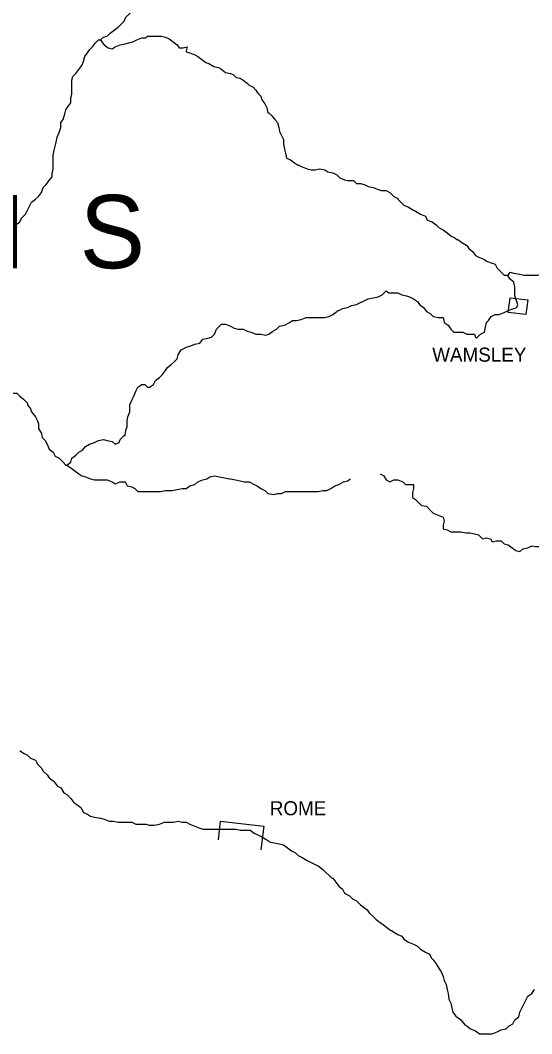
# Model space of a CAD drawing. Extents: x 0 to 40.2, y 0 to 22.
# Drawn here: x 4.348 to 5.056, y 15.833 to 17.238 of the extents above; entities that cross this region are included whole.
import ezdxf

# ---------------------------------------------------------------- set-up
doc = ezdxf.new("R2010")
doc.units = 0
doc.layers.add('Default', color=7, linetype='Continuous')
doc.layers.add('TR_Turning_Path1', color=7, linetype='Continuous')

msp = doc.modelspace()

# ---------------------------------------------------------------- linework, layer by layer
at = {"layer": 'Default'}
for points in [[(4.4914, 17.2361), (4.4941, 17.2416), (4.4996, 17.247), (4.5023, 17.2511), (4.5064, 17.2566), (4.5105, 17.262), (4.5146, 17.2675), (4.5187, 17.2716), (4.5214, 17.2784), (4.5268, 17.2825), (4.5296, 17.2879), (4.5337, 17.2934), (4.5364, 17.2975), (4.5418, 17.3043), (4.5432, 17.3084), (4.5459, 17.3139), (4.5487, 17.3179), (4.5487, 17.3193)], [(4.4587, 17.2102), (4.4628, 17.2143), (4.4682, 17.2157), (4.4723, 17.2198), (4.4778, 17.2239), (4.4832, 17.228), (4.4859, 17.2307), (4.4914, 17.2361), (4.4914, 17.2361)], [(4.3919, 17.0248), (4.3932, 17.0316), (4.3932, 17.0371), (4.3932, 17.0439), (4.3932, 17.0507), (4.3946, 17.0575), (4.396, 17.063), (4.3973, 17.0684), (4.3987, 17.0753), (4.4014, 17.0821), (4.4041, 17.0889), (4.4041, 17.0957), (4.4069, 17.0998), (4.4096, 17.108), (4.411, 17.1134), (4.4137, 17.1175), (4.4178, 17.123), (4.4178, 17.1298), (4.4191, 17.1352), (4.4191, 17.1421), (4.4191, 17.1489), (4.4191, 17.1543), (4.4205, 17.1598), (4.4246, 17.1639), (4.4287, 17.1693), (4.4328, 17.1748), (4.4355, 17.1802), (4.4369, 17.1871), (4.4409, 17.1925), (4.4437, 17.1966), (4.4478, 17.2007), (4.4519, 17.2061), (4.4559, 17.2102), (4.4559, 17.2102), (4.4587, 17.2102)], [(4.4587, 17.2102), (4.4614, 17.2061), (4.4641, 17.2034)], [(4.4641, 17.2034), (4.4696, 17.1993), (4.475, 17.198), (4.4791, 17.2007), (4.4859, 17.2034), (4.4928, 17.2048), (4.4982, 17.2061), (4.5037, 17.2075), (4.5091, 17.2102), (4.5159, 17.213), (4.5214, 17.213), (4.5241, 17.2157), (4.5309, 17.2157), (4.5364, 17.2157), (4.5432, 17.2157), (4.5487, 17.2143), (4.5541, 17.2116), (4.5596, 17.2075), (4.565, 17.2034), (4.5677, 17.1993), (4.5732, 17.1993), (4.5787, 17.2007), (4.5773, 17.1952), (4.5773, 17.1939)], [(4.5773, 17.1939), (4.5827, 17.1925), (4.5896, 17.1898), (4.5937, 17.1871), (4.5991, 17.183), (4.6046, 17.1789), (4.6086, 17.1775), (4.6155, 17.1734), (4.6223, 17.1721), (4.625, 17.1707), (4.6318, 17.1652), (4.6386, 17.1639), (4.6427, 17.1625), (4.6468, 17.1584), (4.6523, 17.1571), (4.6564, 17.1543), (4.6618, 17.1502), (4.6645, 17.1475), (4.67, 17.1448), (4.6741, 17.1407), (4.6768, 17.1366), (4.6809, 17.1325), (4.6823, 17.1271), (4.6864, 17.1216), (4.6891, 17.1162), (4.6905, 17.1093), (4.6918, 17.1093)], [(4.6918, 17.1093), (4.6959, 17.1052), (4.7, 17.0998), (4.7041, 17.0957), (4.7055, 17.0889), (4.7068, 17.0834), (4.7095, 17.078), (4.7123, 17.0725), (4.7123, 17.0657), (4.7136, 17.0589), (4.715, 17.0534), (4.7164, 17.0466), (4.7218, 17.0439), (4.7273, 17.0398), (4.7314, 17.0371), (4.7314, 17.0371), (4.7327, 17.0371)], [(4.7327, 17.0371), (4.7382, 17.0344), (4.745, 17.0316), (4.7504, 17.0303), (4.7559, 17.0303), (4.7627, 17.0316), (4.7695, 17.0303), (4.7736, 17.0275), (4.7804, 17.0262), (4.7859, 17.0234), (4.79, 17.0194), (4.7968, 17.0166), (4.8009, 17.0153), (4.8091, 17.0153), (4.8132, 17.0112), (4.8186, 17.0112), (4.8241, 17.0098), (4.8295, 17.0071), (4.8363, 17.0057), (4.8432, 17.003), (4.8472, 17.0016), (4.8541, 17.0016), (4.8595, 16.9989), (4.865, 16.9934), (4.8704, 16.9907), (4.8704, 16.9894)], [(4.3114, 16.9444), (4.3182, 16.9485), (4.3223, 16.9498), (4.3305, 16.9498), (4.336, 16.9498), (4.3414, 16.9539), (4.3469, 16.958), (4.3496, 16.9635), (4.3551, 16.9689), (4.3578, 16.9744), (4.3605, 16.9798), (4.3632, 16.9853), (4.3687, 16.9894), (4.3728, 16.9934), (4.3769, 16.9989), (4.3796, 17.0057), (4.3837, 17.0098), (4.3878, 17.0153), (4.3919, 17.0207), (4.3919, 17.0248)], [(4.8704, 16.9894), (4.8745, 16.9853), (4.8786, 16.9812), (4.8854, 16.9785), (4.8922, 16.9744), (4.895, 16.973), (4.9018, 16.9689), (4.9086, 16.9662), (4.9113, 16.9607), (4.9181, 16.958), (4.9236, 16.9539), (4.9277, 16.9498), (4.9331, 16.9471), (4.9386, 16.943), (4.944, 16.9389), (4.9495, 16.9362), (4.9522, 16.9335), (4.9536, 16.9335)], [(4.9536, 16.9335), (4.959, 16.9294), (4.9659, 16.9253), (4.9686, 16.9212), (4.974, 16.9171), (4.9781, 16.9116), (4.9836, 16.9089), (4.9904, 16.9062), (4.9931, 16.9035), (5.0013, 16.9007), (5.0054, 16.8994), (5.0081, 16.8939), (5.0136, 16.8885), (5.0177, 16.8844), (5.0231, 16.8844)], [(4.9795, 16.7971), (4.985, 16.8026), (4.9904, 16.8053), (4.9918, 16.8121), (4.9931, 16.8189), (4.9959, 16.8217), (4.9999, 16.8271), (5.0054, 16.8298), (5.0109, 16.8298), (5.0177, 16.8326), (5.0231, 16.8353), (5.0313, 16.838), (5.0354, 16.8394), (5.0368, 16.8435), (5.034, 16.8517), (5.0327, 16.8557), (5.0327, 16.8626), (5.0327, 16.868), (5.0313, 16.8748), (5.0259, 16.8789), (5.0231, 16.883), (5.0231, 16.8844), (5.0231, 16.8844)], [(5.0231, 16.8844), (5.0259, 16.8885), (5.0313, 16.8871), (5.0395, 16.8857), (5.0449, 16.8844), (5.0504, 16.8844), (5.0572, 16.8844), (5.064, 16.8844), (5.0681, 16.8857), (5.0681, 16.8857)], [(4.7886, 16.8353), (4.7941, 16.838), (4.8009, 16.8394), (4.8063, 16.8421), (4.8132, 16.8435), (4.8186, 16.8462), (4.8241, 16.8489), (4.8295, 16.8517), (4.8363, 16.853), (4.8432, 16.8544), (4.8486, 16.8571), (4.8541, 16.8626), (4.8582, 16.8598), (4.8595, 16.8598)], [(4.8595, 16.8598), (4.8636, 16.8598), (4.8704, 16.8598), (4.8759, 16.8571), (4.8827, 16.8557), (4.8868, 16.8544), (4.8922, 16.8517), (4.8977, 16.8476), (4.9004, 16.8435), (4.9004, 16.8435)], [(5.0259, 16.853), (5.0504, 16.8503), (5.0477, 16.8298), (5.0231, 16.8326), (5.0259, 16.853)], [(4.9004, 16.8435), (4.9059, 16.8394), (4.91, 16.8339), (4.9154, 16.8312), (4.9195, 16.8271), (4.9263, 16.8257), (4.9331, 16.8257), (4.9345, 16.8189), (4.94, 16.8148), (4.944, 16.8094), (4.9481, 16.8053), (4.9522, 16.8053), (4.9604, 16.8053), (4.9659, 16.8026), (4.9713, 16.8026), (4.9768, 16.8026), (4.9781, 16.7985), (4.9795, 16.7971)], [(4.6264, 16.8162), (4.6318, 16.8162), (4.6386, 16.8135), (4.6441, 16.8108), (4.6496, 16.8094), (4.6564, 16.8094), (4.6618, 16.8067), (4.6673, 16.8053), (4.6741, 16.8026), (4.6809, 16.8026), (4.6877, 16.8012), (4.6918, 16.8026), (4.6973, 16.8067), (4.7027, 16.8094), (4.7068, 16.8135), (4.7136, 16.8148), (4.7204, 16.8189), (4.7245, 16.8217), (4.73, 16.8217), (4.7368, 16.823), (4.7436, 16.8257), (4.7491, 16.8257), (4.7559, 16.8257), (4.7627, 16.8257), (4.7695, 16.8257), (4.775, 16.8271), (4.7804, 16.8298), (4.7859, 16.8339), (4.7873, 16.8353), (4.7886, 16.8353)], [(4.5732, 16.7821), (4.5787, 16.7848), (4.5841, 16.7862), (4.5896, 16.7889), (4.5964, 16.7903), (4.6005, 16.7958), (4.6073, 16.7971), (4.6127, 16.7985), (4.6168, 16.8026), (4.6196, 16.8094), (4.6236, 16.8135), (4.6264, 16.8162)], [(4.5268, 16.7289), (4.5323, 16.733), (4.535, 16.7385), (4.5405, 16.7426), (4.5446, 16.7467), (4.5487, 16.7521), (4.5514, 16.7562), (4.5568, 16.7603), (4.5609, 16.7644), (4.565, 16.7685), (4.5664, 16.7739), (4.5705, 16.7808), (4.5732, 16.7821)], [(4.4928, 16.6635), (4.4941, 16.669), (4.4955, 16.6744), (4.4955, 16.6826), (4.4968, 16.688), (4.4996, 16.6949), (4.4996, 16.699), (4.4996, 16.7044), (4.5023, 16.7112), (4.505, 16.7167), (4.5078, 16.7235), (4.5105, 16.7289), (4.5159, 16.733), (4.52, 16.733), (4.5241, 16.7289), (4.5268, 16.7289), (4.5268, 16.7289)], [(4.2569, 16.7044), (4.2623, 16.7044), (4.2705, 16.7044), (4.276, 16.7044), (4.2814, 16.703), (4.2882, 16.7044), (4.2951, 16.7071), (4.3005, 16.7099), (4.306, 16.7126), (4.3114, 16.7153), (4.3182, 16.7167), (4.3237, 16.7194), (4.3305, 16.7208), (4.3373, 16.7208), (4.3428, 16.7208), (4.3469, 16.7167), (4.3523, 16.7126), (4.3578, 16.7071), (4.3578, 16.7044)], [(4.3578, 16.7044), (4.3619, 16.699), (4.3632, 16.6949), (4.3687, 16.688), (4.3714, 16.6826), (4.3728, 16.6785), (4.3728, 16.6717), (4.3769, 16.6649), (4.3782, 16.6594), (4.3823, 16.6553), (4.385, 16.6499), (4.3878, 16.6431), (4.3932, 16.639), (4.396, 16.6335), (4.4014, 16.6308), (4.4069, 16.6253), (4.411, 16.6212), (4.4123, 16.6212), (4.4123, 16.6212)], [(4.4123, 16.6212), (4.4178, 16.6253), (4.4191, 16.6308), (4.4246, 16.6349), (4.4287, 16.639), (4.4341, 16.6417), (4.4382, 16.6471), (4.4437, 16.6499), (4.4505, 16.6526), (4.4559, 16.6553), (4.4628, 16.6567), (4.4682, 16.6553), (4.475, 16.654), (4.4791, 16.6499), (4.4846, 16.6526), (4.4859, 16.6567), (4.4914, 16.6621), (4.4928, 16.6621), (4.4928, 16.6635)], [(4.4123, 16.6212), (4.4178, 16.6171), (4.4232, 16.6131), (4.4287, 16.609), (4.4328, 16.6062), (4.4382, 16.6049), (4.445, 16.6021), (4.4505, 16.6008), (4.4559, 16.6008), (4.4628, 16.6008), (4.4682, 16.6008), (4.475, 16.5981), (4.4791, 16.5953), (4.4859, 16.5981), (4.4928, 16.5981), (4.4955, 16.5926), (4.5023, 16.5912), (4.5064, 16.5885), (4.5105, 16.5844), (4.5173, 16.5844), (4.5241, 16.5844), (4.5296, 16.5844), (4.5364, 16.5844), (4.5418, 16.5844), (4.5487, 16.5858), (4.5514, 16.5858)], [(4.5514, 16.5858), (4.5582, 16.5858), (4.565, 16.5871), (4.5718, 16.5885), (4.5773, 16.5885), (4.5827, 16.5926), (4.5896, 16.594), (4.5937, 16.5981), (4.6005, 16.6008), (4.6059, 16.6021), (4.61, 16.6049), (4.6168, 16.6062), (4.6236, 16.6049), (4.6305, 16.6035), (4.6373, 16.6021), (4.6386, 16.6021)], [(4.6386, 16.6021), (4.6455, 16.6008), (4.6523, 16.5994), (4.6577, 16.5981), (4.6645, 16.5981), (4.6714, 16.594), (4.6755, 16.5926), (4.6809, 16.5885), (4.6864, 16.5858), (4.6905, 16.5817), (4.6986, 16.5803), (4.7041, 16.5817), (4.7095, 16.5817), (4.715, 16.5844), (4.715, 16.5844), (4.715, 16.5844)], [(4.715, 16.5844), (4.7204, 16.5844), (4.7286, 16.5844), (4.7354, 16.5844), (4.7409, 16.5844), (4.7464, 16.5844), (4.7532, 16.5844), (4.76, 16.5844), (4.7668, 16.5858), (4.7723, 16.5858), (4.7777, 16.5885), (4.7832, 16.5926), (4.7886, 16.594), (4.7954, 16.5981), (4.8009, 16.5994), (4.805, 16.6021), (4.805, 16.6021)], [(4.8459, 16.609), (4.8513, 16.6062), (4.8541, 16.6008), (4.8595, 16.5981), (4.865, 16.6008), (4.8704, 16.6008), (4.8772, 16.5981), (4.8813, 16.594), (4.8868, 16.594), (4.8922, 16.594), (4.8922, 16.5885), (4.8909, 16.5831), (4.8909, 16.5776), (4.8909, 16.5762)], [(4.8909, 16.5762), (4.895, 16.5735), (4.9004, 16.5681), (4.9031, 16.5653), (4.91, 16.564), (4.9154, 16.5585), (4.9195, 16.5544), (4.9263, 16.5517), (4.9331, 16.549), (4.9345, 16.5435), (4.9331, 16.5381), (4.9331, 16.5326), (4.9386, 16.5312), (4.9386, 16.5312)], [(4.9386, 16.5312), (4.944, 16.5285), (4.9509, 16.5285), (4.9577, 16.5285), (4.9645, 16.5272), (4.97, 16.5272), (4.9768, 16.5258), (4.9822, 16.5244), (4.9877, 16.519), (4.9931, 16.5203), (4.9986, 16.519), (5.0013, 16.5149), (5.0068, 16.5163), (5.0081, 16.5163)], [(5.0081, 16.5163), (5.0136, 16.5163), (5.0177, 16.5122), (5.0231, 16.5108), (5.0286, 16.5067), (5.034, 16.5026), (5.0395, 16.5013), (5.0436, 16.5053), (5.0504, 16.5067), (5.0559, 16.5094), (5.0613, 16.5081), (5.064, 16.5081), (5.0668, 16.5081)], [(4.3469, 16.2258), (4.3523, 16.2218), (4.3578, 16.219), (4.3619, 16.2149), (4.3687, 16.2122), (4.3714, 16.2068), (4.3769, 16.2013), (4.3796, 16.1972), (4.385, 16.1918), (4.3878, 16.1877), (4.3932, 16.1836), (4.3932, 16.1836), (4.3946, 16.1822)], [(4.3946, 16.1822), (4.3987, 16.1768), (4.4041, 16.174), (4.4082, 16.1672), (4.4123, 16.1645), (4.4178, 16.159), (4.4219, 16.1536), (4.4259, 16.1509), (4.4314, 16.1468), (4.4355, 16.1399), (4.4409, 16.1372), (4.445, 16.1345), (4.4505, 16.1331), (4.4587, 16.1318), (4.4641, 16.1304), (4.4709, 16.1277), (4.4764, 16.1277), (4.4832, 16.1263), (4.4887, 16.1263), (4.4955, 16.1263), (4.5023, 16.1263), (4.5078, 16.1236), (4.5159, 16.1236), (4.5214, 16.1236), (4.5268, 16.1222), (4.5337, 16.1222), (4.5405, 16.1236), (4.5473, 16.1263), (4.5514, 16.1263), (4.5596, 16.1263), (4.5664, 16.1277), (4.5718, 16.1263), (4.5773, 16.1263), (4.5827, 16.1236), (4.5896, 16.1209), (4.5964, 16.1181), (4.6005, 16.1168), (4.6073, 16.1168), (4.6141, 16.1168), (4.6223, 16.1168), (4.6264, 16.1168), (4.6332, 16.1168), (4.64, 16.1168), (4.6468, 16.1168), (4.6523, 16.1154), (4.6577, 16.1154), (4.6645, 16.1154), (4.6659, 16.1154)], [(4.6223, 16.1018), (4.625, 16.1277), (4.685, 16.1209), (4.6809, 16.0881)], [(4.6659, 16.1154), (4.6714, 16.1113), (4.6768, 16.1086), (4.6823, 16.1059), (4.6891, 16.1018), (4.6932, 16.099), (4.6986, 16.0977), (4.7068, 16.0963), (4.7123, 16.095), (4.7177, 16.0909), (4.7232, 16.0868), (4.7286, 16.084), (4.7327, 16.08), (4.7382, 16.0772), (4.745, 16.0731), (4.7504, 16.0704), (4.7559, 16.0677), (4.7614, 16.065), (4.7668, 16.0609), (4.7709, 16.0568), (4.775, 16.0527), (4.7791, 16.0486), (4.7791, 16.0486), (4.7804, 16.0486)], [(4.7804, 16.0486), (4.7845, 16.0431), (4.7886, 16.0377), (4.7941, 16.0336), (4.7968, 16.0281), (4.8036, 16.0241), (4.8077, 16.02), (4.8132, 16.0172), (4.8186, 16.0118), (4.8227, 16.0091), (4.8282, 16.005), (4.8309, 16.0009), (4.8363, 15.9954), (4.8404, 15.9913), (4.8459, 15.9872), (4.85, 15.9845), (4.8554, 15.9804), (4.8609, 15.9763), (4.8622, 15.9763), (4.8636, 15.975)], [(4.8636, 15.975), (4.8704, 15.9709), (4.8759, 15.9682), (4.8786, 15.9641), (4.8854, 15.96), (4.8922, 15.9572), (4.8977, 15.9545), (4.9018, 15.9504), (4.9086, 15.9463), (4.9141, 15.9436), (4.9168, 15.9382), (4.9195, 15.9354), (4.9236, 15.93), (4.9277, 15.9232), (4.9304, 15.9191), (4.9331, 15.9123), (4.9345, 15.9068), (4.9372, 15.9013), (4.9386, 15.8945), (4.94, 15.8891), (4.9413, 15.8809), (4.944, 15.8754), (4.9454, 15.8686), (4.9468, 15.8632), (4.9509, 15.8577), (4.9522, 15.8564), (4.9522, 15.8564)], [(4.9522, 15.8564), (4.9577, 15.8523), (4.9631, 15.8454), (4.9659, 15.8441), (4.9713, 15.84), (4.9781, 15.8373), (4.9836, 15.8332), (4.9904, 15.8332), (4.9959, 15.8332), (5.0013, 15.8332), (5.0081, 15.8359), (5.0136, 15.8386), (5.0204, 15.84), (5.0245, 15.8441), (5.0299, 15.8468), (5.0327, 15.8523), (5.0381, 15.8564), (5.0395, 15.8632), (5.0422, 15.8686), (5.0449, 15.8741), (5.0477, 15.8795), (5.0504, 15.885), (5.0559, 15.8891), (5.0599, 15.8945)]]:
    msp.add_lwpolyline(points, dxfattribs=at)

# ---------------------------------------------------------------- texts
for s, p in [('WAMSLEY', (4.9181, 16.7644)), ('ROME', (4.6932, 16.1359))]:
    msp.add_text(s, height=0.0195, dxfattribs=at).set_placement(p)
at = {"layer": 'TR_Turning_Path1'}
msp.add_text('A  D  A  M  S', height=0.101489, dxfattribs=at).set_placement((3.7362, 16.8939))

doc.saveas('drawing.dxf')
